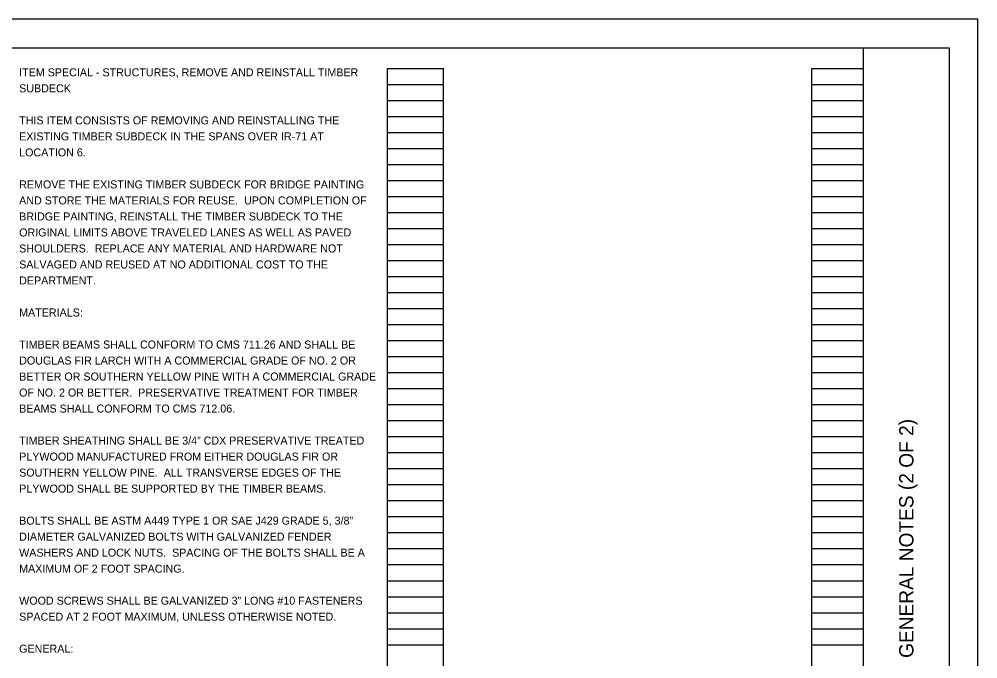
# Model space of a CAD drawing. Extents: x 0 to 65, y -0.7 to 22.
# Drawn here: x 17.24 to 34, y 10.81 to 22 of the extents above; entities that cross this region are included whole.
import ezdxf

# ---------------------------------------------------------------- set-up
doc = ezdxf.new("R2010")
doc.units = 0
for name, color, linetype in [('SH_Border', 7, 'Continuous'), ('SH_Cut_Line', 7, 'Continuous'), ('SH_Text', 7, 'Continuous')]:
    doc.layers.add(name, color=color, linetype=linetype)

msp = doc.modelspace()

# ---------------------------------------------------------------- linework, layer by layer
at = {"layer": 'SH_Border'}
for p, q in [((23.68, 0.98), (23.68, 21.14)), ((23.68, 21.14), (24.66, 21.14)), ((24.66, 0.98), (24.66, 21.14)), ((31.1, 0.98), (31.1, 21.14)), ((31.1, 21.14), (32, 21.14)), ((32, 0.98), (32, 21.14)), ((23.68, 20.86), (24.66, 20.86)), ((31.1, 20.86), (32, 20.86)), ((23.68, 20.58), (24.66, 20.58)), ((31.1, 20.58), (32, 20.58)), ((23.68, 20.3), (24.66, 20.3)), ((31.1, 20.3), (32, 20.3)), ((23.68, 20.02), (24.66, 20.02)), ((31.1, 20.02), (32, 20.02)), ((23.68, 19.74), (24.66, 19.74)), ((31.1, 19.74), (32, 19.74)), ((23.68, 19.46), (24.66, 19.46)), ((31.1, 19.46), (32, 19.46)), ((23.68, 19.18), (24.66, 19.18)), ((31.1, 19.18), (32, 19.18)), ((23.68, 18.9), (24.66, 18.9)), ((31.1, 18.9), (32, 18.9)), ((23.68, 18.62), (24.66, 18.62)), ((31.1, 18.62), (32, 18.62)), ((23.68, 18.34), (24.66, 18.34)), ((31.1, 18.34), (32, 18.34)), ((23.68, 18.06), (24.66, 18.06)), ((31.1, 18.06), (32, 18.06)), ((23.68, 17.78), (24.66, 17.78)), ((31.1, 17.78), (32, 17.78)), ((23.68, 17.5), (24.66, 17.5)), ((31.1, 17.5), (32, 17.5)), ((23.68, 17.22), (24.66, 17.22)), ((31.1, 17.22), (32, 17.22)), ((23.68, 16.94), (24.66, 16.94)), ((31.1, 16.94), (32, 16.94)), ((23.68, 16.66), (24.66, 16.66)), ((31.1, 16.66), (32, 16.66)), ((23.68, 16.38), (24.66, 16.38)), ((31.1, 16.38), (32, 16.38)), ((23.68, 16.1), (24.66, 16.1)), ((31.1, 16.1), (32, 16.1)), ((23.68, 15.82), (24.66, 15.82)), ((31.1, 15.82), (32, 15.82)), ((23.68, 15.54), (24.66, 15.54)), ((31.1, 15.54), (32, 15.54)), ((23.68, 15.26), (24.66, 15.26)), ((31.1, 15.26), (32, 15.26)), ((23.68, 14.98), (24.66, 14.98)), ((31.1, 14.98), (32, 14.98)), ((23.68, 14.7), (24.66, 14.7)), ((31.1, 14.7), (32, 14.7)), ((23.68, 14.42), (24.66, 14.42)), ((31.1, 14.42), (32, 14.42)), ((23.68, 14.14), (24.66, 14.14)), ((31.1, 14.14), (32, 14.14)), ((23.68, 13.86), (24.66, 13.86)), ((31.1, 13.86), (32, 13.86)), ((23.68, 13.58), (24.66, 13.58)), ((31.1, 13.58), (32, 13.58)), ((23.68, 13.3), (24.66, 13.3)), ((31.1, 13.3), (32, 13.3)), ((23.68, 13.02), (24.66, 13.02)), ((31.1, 13.02), (32, 13.02)), ((23.68, 12.74), (24.66, 12.74)), ((31.1, 12.74), (32, 12.74)), ((23.68, 12.46), (24.66, 12.46)), ((31.1, 12.46), (32, 12.46)), ((23.68, 12.18), (24.66, 12.18)), ((31.1, 12.18), (32, 12.18)), ((23.68, 11.9), (24.66, 11.9)), ((31.1, 11.9), (32, 11.9)), ((23.68, 11.62), (24.66, 11.62)), ((31.1, 11.62), (32, 11.62)), ((23.68, 11.34), (24.66, 11.34)), ((31.1, 11.34), (32, 11.34)), ((23.68, 11.06), (24.66, 11.06)), ((31.1, 11.06), (32, 11.06))]:
    msp.add_line(p, q, dxfattribs=at)
at = {"layer": 'SH_Cut_Line'}
msp.add_line((32, 0.5), (32, 21.5), dxfattribs=at)
msp.add_lwpolyline([(1.5, 21.5), (33.5, 21.5), (33.5, 0.5), (1.5, 0.5)], close=True, dxfattribs=at)
at = {"layer": 'SH_Text'}
msp.add_lwpolyline([(0, 0), (34, 0), (34, 22), (0, 22)], close=True, dxfattribs=at)

# ---------------------------------------------------------------- texts
at = {"layer": 'SH_Border'}
msp.add_text('GENERAL NOTES (2 OF 2)', height=0.25, rotation=90, dxfattribs=at).set_placement((32.875, 10.829))
at = {"layer": 'SH_Text'}
for s, p in [('ITEM SPECIAL - STRUCTURES, REMOVE AND REINSTALL TIMBER ', (17.24, 21)), ('SUBDECK', (17.24, 20.72)), ('THIS ITEM CONSISTS OF REMOVING AND REINSTALLING THE ', (17.24, 20.16)), ('EXISTING TIMBER SUBDECK IN THE SPANS OVER IR-71 AT ', (17.24, 19.88)), ('LOCATION 6.', (17.24, 19.6)), ('REMOVE THE EXISTING TIMBER SUBDECK FOR BRIDGE PAINTING ', (17.24, 19.04)), ('AND STORE THE MATERIALS FOR REUSE.  UPON COMPLETION OF ', (17.24, 18.76)), ('BRIDGE PAINTING, REINSTALL THE TIMBER SUBDECK TO THE ', (17.24, 18.48)), ('ORIGINAL LIMITS ABOVE TRAVELED LANES AS WELL AS PAVED ', (17.24, 18.2)), ('SHOULDERS.  REPLACE ANY MATERIAL AND HARDWARE NOT ', (17.24, 17.92)), ('SALVAGED AND REUSED AT NO ADDITIONAL COST TO THE ', (17.24, 17.64)), ('DEPARTMENT.', (17.24, 17.36)), ('MATERIALS:', (17.24, 16.8)), ('TIMBER BEAMS SHALL CONFORM TO CMS 711.26 AND SHALL BE ', (17.24, 16.24)), ('DOUGLAS FIR LARCH WITH A COMMERCIAL GRADE OF NO. 2 OR ', (17.24, 15.96)), ('BETTER OR SOUTHERN YELLOW PINE WITH A COMMERCIAL GRADE ', (17.24, 15.68)), ('OF NO. 2 OR BETTER.  PRESERVATIVE TREATMENT FOR TIMBER ', (17.24, 15.4)), ('BEAMS SHALL CONFORM TO CMS 712.06.', (17.24, 15.12)), ('TIMBER SHEATHING SHALL BE 3/4” CDX PRESERVATIVE TREATED ', (17.24, 14.56)), ('PLYWOOD MANUFACTURED FROM EITHER DOUGLAS FIR OR ', (17.24, 14.28)), ('SOUTHERN YELLOW PINE.  ALL TRANSVERSE EDGES OF THE ', (17.24, 14)), ('PLYWOOD SHALL BE SUPPORTED BY THE TIMBER BEAMS.', (17.24, 13.72)), ('BOLTS SHALL BE ASTM A449 TYPE 1 OR SAE J429 GRADE 5, 3/8” ', (17.24, 13.16)), ('DIAMETER GALVANIZED BOLTS WITH GALVANIZED FENDER ', (17.24, 12.88)), ('WASHERS AND LOCK NUTS.  SPACING OF THE BOLTS SHALL BE A ', (17.24, 12.6)), ('MAXIMUM OF 2 FOOT SPACING.', (17.24, 12.32)), ('WOOD SCREWS SHALL BE GALVANIZED 3” LONG #10 FASTENERS ', (17.24, 11.76)), ('SPACED AT 2 FOOT MAXIMUM, UNLESS OTHERWISE NOTED.', (17.24, 11.48)), ('GENERAL:', (17.24, 10.92))]:
    msp.add_text(s, height=0.14, dxfattribs=at).set_placement(p)

doc.saveas('drawing.dxf')
